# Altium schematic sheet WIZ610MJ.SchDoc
size 304 x 215 mm
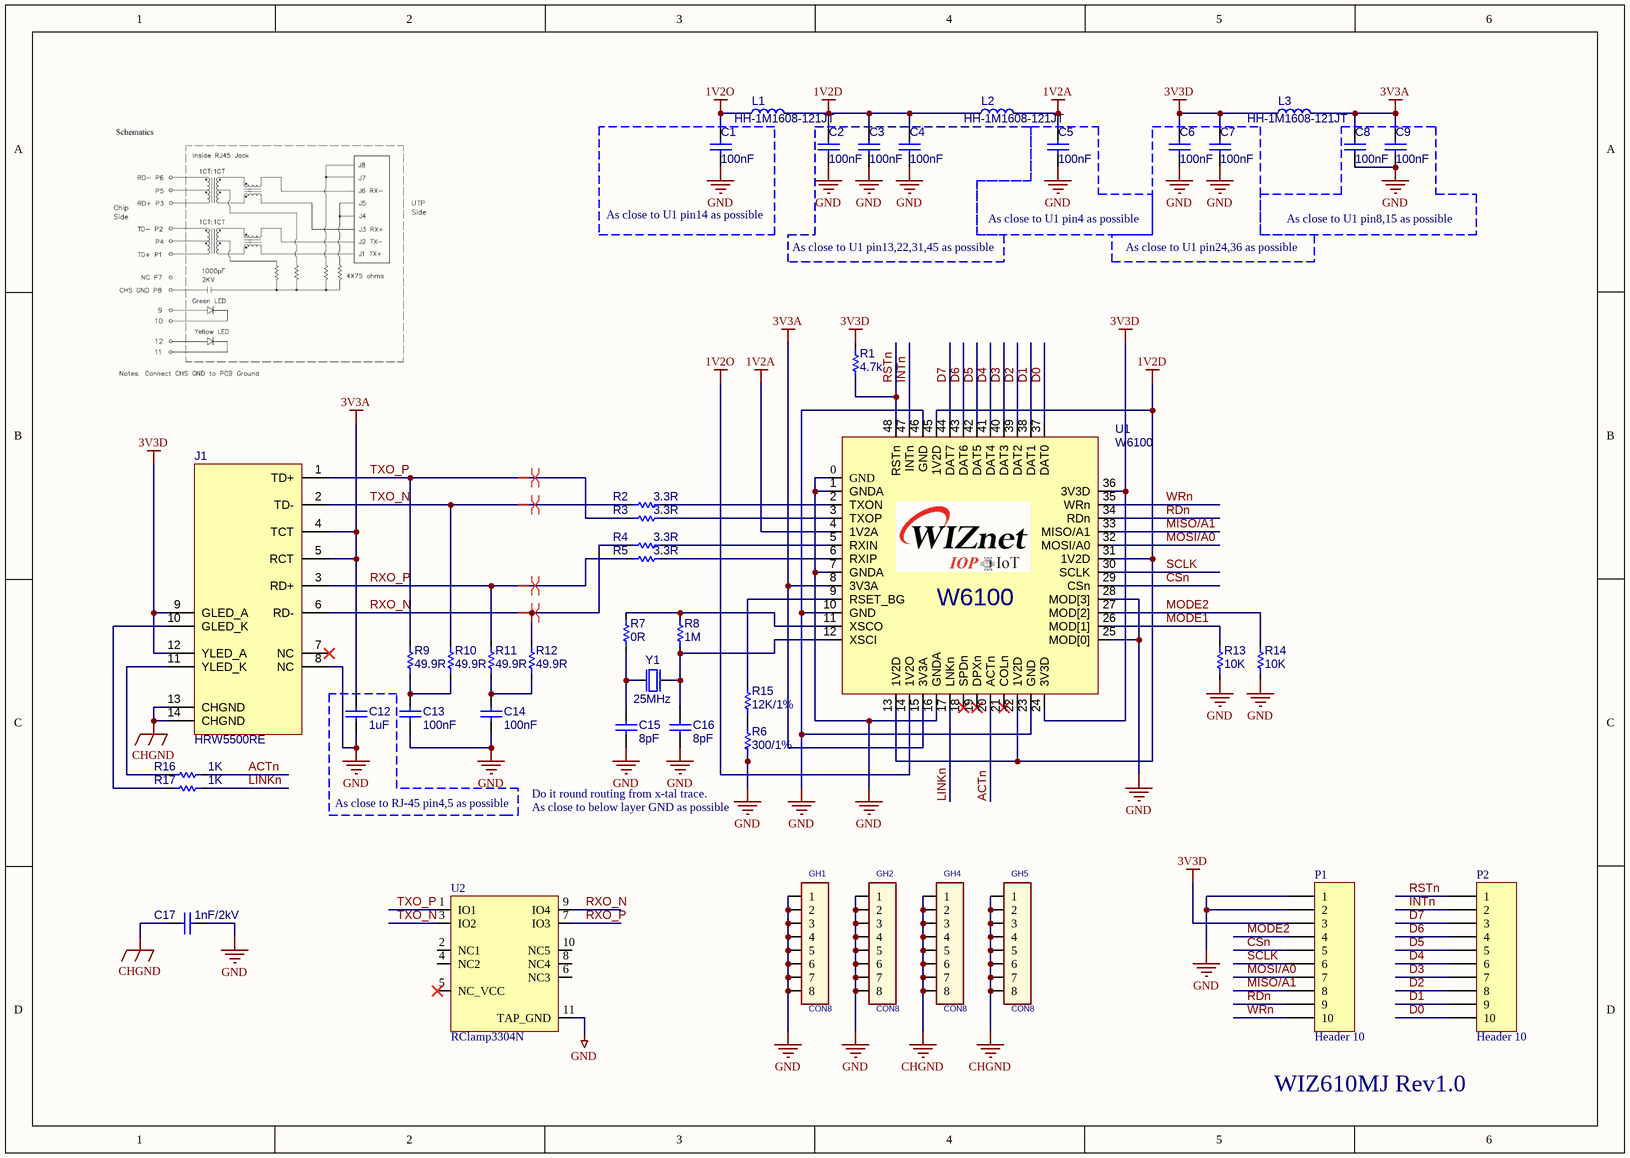
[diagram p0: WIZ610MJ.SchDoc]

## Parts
C1  100nF  [0603-C]
C2  100nF  [0603-C]
C3  100nF  [0603-C]
C4  100nF  [0603-C]
C5  100nF  [0603-C]
C6  100nF  [0603-C]
C7  100nF  [0603-C]
C8  100nF  [0603-C]
C9  100nF  [0603-C]
C12  1uF  [0603-C]
C13  100nF  [0603-C]
C14  100nF  [0603-C]
C15  8pF  [0603-C]
C16  8pF  [0603-C]
C17  1nF/2kV  [CAP-1808]
GH1  CON8  [定位孔（带小孔）]
GH2  CON8  [定位孔（带小孔）]
GH4  CON8  [定位孔（带小孔）]
GH5  CON8  [定位孔（带小孔）]
J1  HRW5500RE  [RJ-45(HRW5500RE)]
L1  HH-1M1608-121JT  [0603-L]
L2  HH-1M1608-121JT  [0603-L]
L3  HH-1M1608-121JT  [0603-L]
P1  Header 10  [HDR1X10]
P2  Header 10  [HDR1X10]
R1  4.7k  [0603-R]
R2  3.3R  [0603-R]
R3  3.3R  [0603-R]
R4  3.3R  [0603-R]
R5  3.3R  [0603-R]
R6  300/1%  [RES-0603]
R7  0R  [0603-R]
R8  1M  [0603-R]
R9  49.9R  [0603-R]
R10  49.9R  [0603-R]
R11  49.9R  [0603-R]
R12  49.9R  [0603-R]
R13  10K  [0603-R]
R14  10K  [0603-R]
R15  12K/1%  [RES-0603]
R16  1K  [0603-R]
R17  1K  [0603-R]
U1  W6100  [WIZNET W5100S QFN]
U2  RClamp3304N  [DFN-10]
Y1  25MHz  [OSC-82J0626]

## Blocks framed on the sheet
As close to U1 pin14 as possible: C1
As close to U1 pin13,22,31,45 as possible: C2-C4
As close to U1 pin4 as possible: C5
As close to U1 pin24,36 as possible: C6 C7
As close to U1 pin8,15 as possible: C8 C9
As close to RJ-45 pin4,5 as possible: C12

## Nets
1V2A: C5.2 L2.2 U1.4(1V2A)
1V2D: C2.2 C3.2 C4.2 L1.2 L2.1 U1.13(1V2D) U1.22(1V2D) U1.31(1V2D) U1.45(1V2D)
1V2O: C1.2 L1.1 U1.14(1V2O)
3V3A: C8.2 C9.2 C12.2 J1.4(TCT) J1.5(RCT) L3.2 U1.8(3V3A) U1.15(3V3A)
3V3D: C6.2 C7.2 J1.9(GLED_A) J1.12(YLED_A) L3.1 P1.3 R1.2 U1.24(3V3D) U1.36(3V3D)
CHGND: C17.1 GH4.1 GH4.2 GH4.3 GH4.4 GH4.5 GH4.6 GH4.7 GH4.8 GH5.1 GH5.2 GH5.3 GH5.4 GH5.5 GH5.6 GH5.7 GH5.8 J1.13(CHGND) J1.14(CHGND)
GND: C1.1 C2.1 C3.1 C4.1 C5.1 C6.1 C7.1 C8.1 C9.1 C12.1 C13.1 C14.1 C15.1 C16.1 C17.2 GH1.1 GH1.2 GH1.3 GH1.4 GH1.5 GH1.6 GH1.7 GH1.8 GH2.1 GH2.2 GH2.3 GH2.4 GH2.5 GH2.6 GH2.7 GH2.8 J1.8(NC) P1.1 P1.2 R6.1 R13.1 R14.1 U1.0(GND) U1.1(GNDA) U1.7(GNDA) U1.10(GND) U1.16(GNDA) U1.23(GND) U1.25(MOD[0]) U1.28(MOD[3]) U1.46(GND) U2.11(TAP_GND) Y1.2(GND) Y1.4(GND)
ACTn: R16.1 U1.20(ACTn)
CSn: P1.5 U1.29(CSn)
D0: P2.10 U1.37(DAT0)
D1: P2.9 U1.38(DAT1)
D2: P2.8 U1.39(DAT2)
D3: P2.7 U1.40(DAT3)
D4: P2.6 U1.41(DAT4)
D5: P2.5 U1.42(DAT5)
D6: P2.4 U1.43(DAT6)
D7: P2.3 U1.44(DAT7)
INTn: P2.2 U1.47(INTn)
LINKn: R17.1 U1.17(LNKn)
MISO/A1: P1.8 U1.33(MISO/A1)
MODE1: R13.2 U1.26(MOD[1])
MODE2: P1.4 R14.2 U1.27(MOD[2])
MOSI/A0: P1.7 U1.32(MOSI/A0)
RDn: P1.9 U1.34(RDn)
RSTn: P2.1 R1.1 U1.48(RSTn)
RXO_N: J1.6(RD-) R4.2 R12.2 U2.9(IO4)
RXO_P: J1.3(RD+) R5.2 R11.2 U2.7(IO3)
SCLK: P1.6 U1.30(SCLK)
TXO_N: J1.2(TD-) R2.2 R10.2 U2.3(IO2)
TXO_P: J1.1(TD+) R3.2 R9.2 U2.1(IO1)
WRn: P1.10 U1.35(WRn)
NetC13_2: C13.2 R9.1 R10.1
NetC14_2: C14.2 R11.1 R12.1
NetC15_2: C15.2 R7.1 Y1.1(inp)
NetC16_2: C16.2 R8.1 U1.12(XSCI) Y1.3(out)
NetJ1_10: J1.10(GLED_K) R17.2
NetJ1_11: J1.11(YLED_K) R16.2
NetR2_1: R2.1 U1.2(TXON)
NetR3_1: R3.1 U1.3(TXOP)
NetR4_1: R4.1 U1.5(RXIN)
NetR5_1: R5.1 U1.6(RXIP)
NetR6_2: R6.2 R15.1
NetR7_2: R7.2 R8.2 U1.11(XSCO)
NetR15_2: R15.2 U1.9(RSET_BG)

Not connected (* = marked no-connect by the designer): J1 7(NC)*; U1 18(SPDn)* 19(DPXn)* 21(COLn)*; U2 2(NC1) 4(NC2) 5(NC_VCC)* 6(NC3) 8(NC4) 10(NC5)

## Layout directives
differential pair: RXO_N, RXO_P, TXO_N, TXO_P

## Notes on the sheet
- Do it round routing from x-tal trace.
- As close to below layer GND as possible
- WIZ610MJ Rev1.0

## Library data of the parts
C1-C9 C12-C16 = CAP-0603: Ceramic CAP 0603(1608)
C17 = CAP-1808: Ceramic CAP 1808(4520)
J1 = 57-00013QL11-1
L1-L3 = IND-0603: Inductor 0603(1608)
P1 P2 = Header 10: Header, 10-Pin
R1-R17 = RES-0603: RES0603
U1 = W6100: WIZnet Hardwired TCP/IP Chip
U2 = RClamp3304N: Ethernet 3.3V TVS diode, Semtech, SLP2626P10
Y1 = OSC-82J0626-25MHz: X-tal 25MHz,3.2x2.5 SMD, CL=18pF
